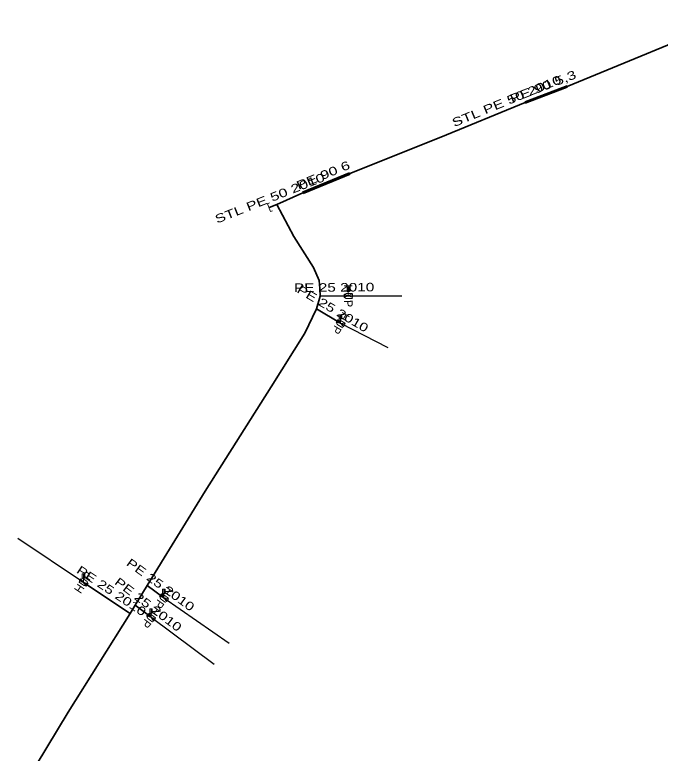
# Model space of a CAD drawing. Extents: x -737484 to -734496, y -1033882 to -1030666.
# Drawn here: x -736434.6 to -736358.7, y -1032421.6 to -1032334.9 of the extents above; entities that cross this region are included whole.
import ezdxf
from ezdxf.enums import TextEntityAlignment as Align

# ---------------------------------------------------------------- set-up
doc = ezdxf.new("R2010")
doc.units = 0
doc.header["$LTSCALE"] = 0.4
for name, color, linetype, lineweight in [('1', 7, 'Continuous', 13), ('18', 7, 'Continuous', 60), ('22', 7, 'Continuous', 25), ('5', 7, 'Continuous', 35), ('7', 7, 'Continuous', 35)]:
    doc.layers.add(name, color=color, linetype=linetype, lineweight=lineweight)
doc.layers.add('2', color=7, linetype='Continuous')

msp = doc.modelspace()

# ---------------------------------------------------------------- linework, layer by layer
at = {"layer": '1'}
for p, q in [((-736395.361, -1032367.873), (-736395.361, -1032367.373)), ((-736395.286, -1032367.298), (-736395.286, -1032366.948)), ((-736396.189, -1032370.518), (-736396.189, -1032370.168)), ((-736396.264, -1032371.093), (-736396.264, -1032370.593)), ((-736426.395, -1032400.985), (-736426.395, -1032400.635)), ((-736426.47, -1032401.56), (-736426.47, -1032401.06)), ((-736417.027, -1032403.354), (-736417.027, -1032402.854)), ((-736416.952, -1032402.779), (-736416.952, -1032402.429)), ((-736418.464, -1032405.08), (-736418.464, -1032404.73)), ((-736418.539, -1032405.655), (-736418.539, -1032405.155))]:
    msp.add_line(p, q, dxfattribs=at)
msp.add_lwpolyline([(-736404.255, -1032357.886), (-736404.487, -1032357.98), (-736404.862, -1032357.053), (-736404.63, -1032356.959)], dxfattribs=at)
for points in [[(-736394.864, -1032367.664), (-736394.857, -1032368.064), (-736395.864, -1032367.681), (-736395.857, -1032368.081)], [(-736395.361, -1032366.873), (-736395.511, -1032366.873), (-736395.511, -1032367.373), (-736395.361, -1032367.373)], [(-736395.361, -1032366.873), (-736395.211, -1032366.873), (-736395.211, -1032367.373), (-736395.361, -1032367.373)], [(-736395.324, -1032366.911), (-736395.249, -1032366.911), (-736395.249, -1032367.336), (-736395.324, -1032367.336)], [(-736396.264, -1032370.093), (-736396.414, -1032370.093), (-736396.414, -1032370.593), (-736396.264, -1032370.593)], [(-736396.264, -1032370.093), (-736396.114, -1032370.093), (-736396.114, -1032370.593), (-736396.264, -1032370.593)], [(-736396.227, -1032370.131), (-736396.152, -1032370.131), (-736396.152, -1032370.556), (-736396.227, -1032370.556)], [(-736395.732, -1032371.179), (-736395.938, -1032371.521), (-736396.589, -1032370.664), (-736396.795, -1032371.006)], [(-736426.47, -1032400.56), (-736426.62, -1032400.56), (-736426.62, -1032401.06), (-736426.47, -1032401.06)], [(-736426.47, -1032400.56), (-736426.32, -1032400.56), (-736426.32, -1032401.06), (-736426.47, -1032401.06)], [(-736426.433, -1032400.598), (-736426.358, -1032400.598), (-736426.358, -1032401.023), (-736426.433, -1032401.023)], [(-736426.996, -1032401.446), (-736426.772, -1032401.114), (-736426.167, -1032402.005), (-736425.943, -1032401.673)], [(-736417.027, -1032402.354), (-736417.177, -1032402.354), (-736417.177, -1032402.854), (-736417.027, -1032402.854)], [(-736417.027, -1032402.354), (-736416.877, -1032402.354), (-736416.877, -1032402.854), (-736417.027, -1032402.854)], [(-736416.504, -1032403.486), (-736416.74, -1032403.809), (-736417.313, -1032402.898), (-736417.549, -1032403.221)], [(-736416.99, -1032402.392), (-736416.915, -1032402.392), (-736416.915, -1032402.817), (-736416.99, -1032402.817)], [(-736418.539, -1032404.655), (-736418.689, -1032404.655), (-736418.689, -1032405.155), (-736418.539, -1032405.155)], [(-736418.539, -1032404.655), (-736418.389, -1032404.655), (-736418.389, -1032405.155), (-736418.539, -1032405.155)], [(-736418.502, -1032404.693), (-736418.427, -1032404.693), (-736418.427, -1032405.118), (-736418.502, -1032405.118)], [(-736418.019, -1032405.796), (-736418.26, -1032406.115), (-736418.817, -1032405.194), (-736419.058, -1032405.513)]]:
    msp.add_lwpolyline(points, close=True, dxfattribs=at)
at = {"layer": '18'}
for p, q in [((-736374.582, -1032345.179), (-736369.657, -1032343.269)), ((-736400.684, -1032355.759), (-736395.181, -1032353.489))]:
    msp.add_line(p, q, dxfattribs=at)
at = {"layer": '22'}
for p, q in [((-736395.361, -1032367.873), (-736389.07, -1032367.861)), ((-736396.264, -1032371.093), (-736390.731, -1032373.96)), ((-736426.47, -1032401.56), (-736434.195, -1032396.412)), ((-736417.027, -1032403.354), (-736409.339, -1032408.708)), ((-736418.539, -1032405.655), (-736411.102, -1032411.176))]:
    msp.add_line(p, q, dxfattribs=at)
at = {"layer": '5'}
msp.add_line((-736404.675, -1032357.517), (-736403.749, -1032357.15), dxfattribs=at)
for points in [[(-736403.749, -1032357.15), (-736400.684, -1032355.759), (-736395.181, -1032353.489), (-736384.49, -1032349.247), (-736374.582, -1032345.179), (-736369.657, -1032343.269), (-736349.842, -1032335.135), (-736348.939, -1032334.854)], [(-736434.551, -1032427.173), (-736428.273, -1032416.819), (-736421.009, -1032405.205), (-736420.406, -1032404.23), (-736418.984, -1032401.932), (-736412.163, -1032390.823), (-736404.44, -1032378.589), (-736400.484, -1032372.269), (-736399.114, -1032369.412), (-736398.666, -1032367.902), (-736398.69, -1032367.02), (-736398.801, -1032366.061), (-736399.463, -1032364.561), (-736401.772, -1032360.916), (-736403.749, -1032357.15)]]:
    msp.add_lwpolyline(points, dxfattribs=at)
at = {"layer": '7'}
for p, q in [((-736398.666, -1032367.902), (-736395.361, -1032367.873)), ((-736399.114, -1032369.412), (-736396.264, -1032371.093)), ((-736421.009, -1032405.205), (-736426.47, -1032401.56)), ((-736418.984, -1032401.932), (-736417.027, -1032403.354)), ((-736420.406, -1032404.23), (-736418.539, -1032405.655))]:
    msp.add_line(p, q, dxfattribs=at)

# ---------------------------------------------------------------- texts
at = {"layer": '18', "width": 1.4}
for s, rotation, p in [('PE 90 5,3', 21.197, (-736372.3003, -1032343.7572)), ('PE 90 6', 22.416, (-736398.1222, -1032354.1614))]:
    msp.add_text(s, height=1, rotation=rotation, dxfattribs=at).set_placement(p, align=Align.CENTER)
at = {"layer": '2', "width": 0.95}
for rotation, p in [(271, (-736395.8608, -1032367.8818)), (239, (-736396.6922, -1032370.835)), (56, (-736426.0551, -1032401.8391)), (234, (-736417.431, -1032403.0596)), (233, (-736418.9375, -1032405.3536))]:
    msp.add_text('HUP', height=1, rotation=rotation, dxfattribs=at).set_placement(p, align=Align.CENTER)
at = {"layer": '5', "width": 1.4}
for rotation, p in [(22.322, (-736376.5674, -1032345.4538)), (21.62, (-736404.3962, -1032356.8678))]:
    msp.add_text('STL PE 50 2010', height=1, rotation=rotation, dxfattribs=at).set_placement(p, align=Align.CENTER)
at = {"layer": '7', "width": 1.35}
for rotation, p in [(0.503, (-736397.0174, -1032367.3869)), (329.467, (-736397.4345, -1032369.821)), (323.997, (-736417.7109, -1032402.2378)), (326.278, (-736423.4616, -1032402.9661)), (322.647, (-736419.1684, -1032404.5445))]:
    msp.add_text('PE 25 2010', height=1, rotation=rotation, dxfattribs=at).set_placement(p, align=Align.CENTER)

doc.saveas('drawing.dxf')
